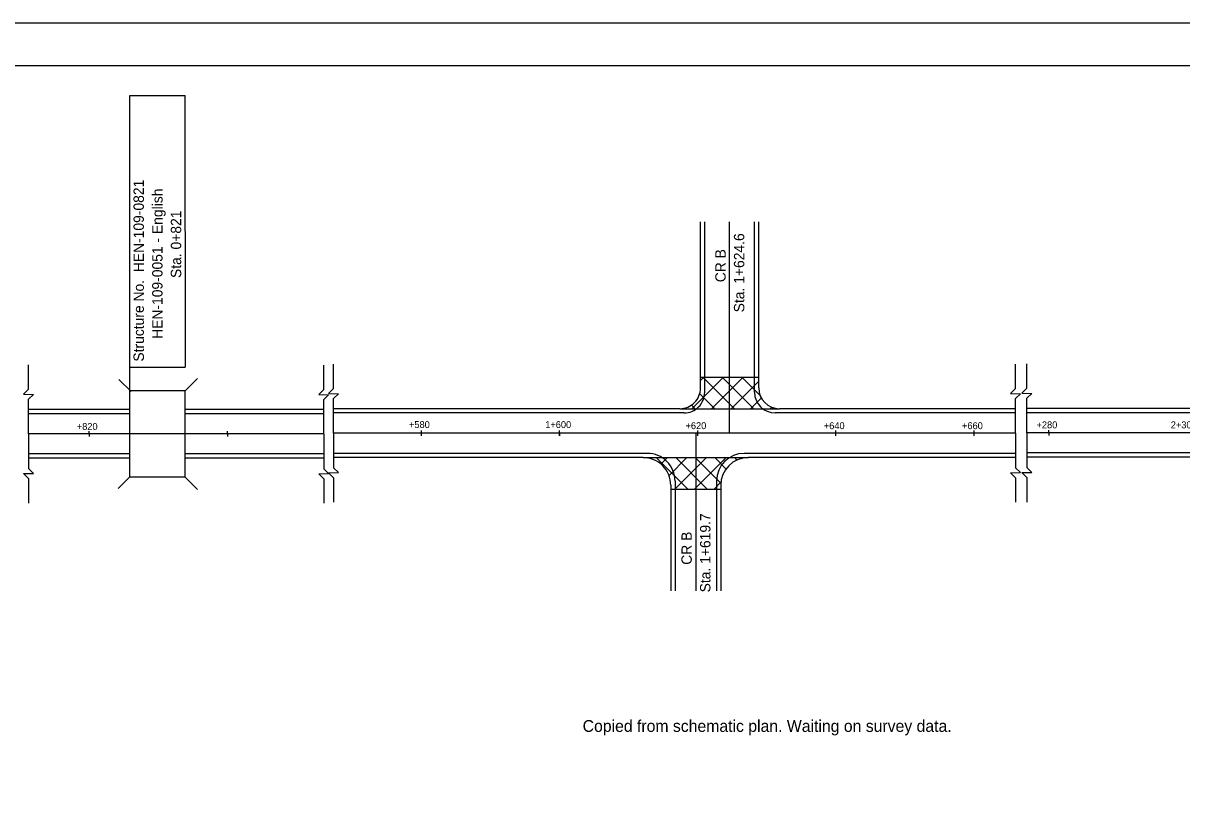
# Model space of a CAD drawing. Extents: x 3 to 683, y -6 to 434.
# Drawn here: x 176.6 to 451.7, y 251.3 to 433.7 of the extents above; entities that cross this region are included whole.
import ezdxf

# ---------------------------------------------------------------- set-up
doc = ezdxf.new("R2010")
doc.units = 0
for name, color, linetype in [('Default', 7, 'Continuous'), ('SH_Border', 7, 'Continuous'), ('SH_Cut_Line', 7, 'Continuous'), ('SH_Text', 7, 'Continuous')]:
    doc.layers.add(name, color=color, linetype=linetype)

msp = doc.modelspace()

# ---------------------------------------------------------------- linework, layer by layer
at = {"layer": 'Default'}
for p, q in [((201.91, 346.51), (201.91, 416.55)), ((201.91, 416.55), (215.04, 416.55)), ((215.06, 352.07), (215.02, 416.55)), ((337.38, 347.15), (337.38, 386.58)), ((338.38, 346.15), (338.38, 386.58)), ((344.28, 336.43), (344.28, 386.58)), ((350.19, 346.15), (350.19, 386.58)), ((351.19, 347.15), (351.19, 386.58)), ((177.82, 346.85), (177.82, 352.66)), ((247.9, 346.79), (247.9, 352.59)), ((250.25, 347.03), (250.25, 352.83)), ((412.16, 347.03), (412.16, 352.83)), ((414.87, 347.1), (414.87, 352.9)), ((201.93, 352.07), (215.05, 352.07)), ((215.04, 346.51), (217.94, 349.41)), ((335.35, 342.23), (342.84, 349.72)), ((337.38, 349.72), (351.19, 349.72)), ((337.38, 348.9), (338.2, 349.72)), ((337.91, 349.72), (345.41, 342.23)), ((339.98, 342.23), (347.48, 349.72)), ((342.55, 349.72), (350.05, 342.23)), ((347.19, 349.72), (351.69, 345.22)), ((176.64, 345.67), (177.82, 346.85)), ((199.26, 349.2), (202.16, 346.3)), ((246.72, 345.6), (247.9, 346.79)), ((249.06, 345.84), (250.25, 347.03)), ((344.62, 342.23), (351.19, 348.79)), ((410.98, 345.84), (412.16, 347.03)), ((413.68, 345.91), (414.87, 347.1)), ((176.64, 345.67), (178.98, 345.62)), ((177.82, 344.46), (178.98, 345.62)), ((177.82, 336.26), (177.82, 344.46)), ((201.91, 326), (201.91, 346.55)), ((215.04, 346.51), (201.91, 346.51)), ((215.04, 326), (215.04, 346.51)), ((246.72, 345.6), (249.06, 345.56)), ((247.9, 344.4), (249.06, 345.56)), ((247.9, 336.19), (247.9, 344.4)), ((249.06, 345.84), (251.41, 345.8)), ((250.25, 344.64), (251.41, 345.8)), ((250.25, 336.43), (250.25, 344.64)), ((337.22, 345.78), (340.77, 342.23)), ((349.26, 342.23), (351.85, 344.82)), ((410.98, 345.84), (413.32, 345.8)), ((412.16, 344.64), (413.32, 345.8)), ((412.16, 336.43), (412.16, 344.64)), ((413.68, 345.91), (416.03, 345.87)), ((414.87, 344.71), (416.03, 345.87)), ((414.87, 336.5), (414.87, 344.71)), ((201.91, 342.01), (177.82, 342.01)), ((247.9, 342.01), (215.04, 342.01)), ((332.45, 342.23), (250.25, 342.24)), ((333.45, 341.23), (250.25, 341.24)), ((332.45, 342.23), (356.11, 342.22)), ((335.25, 343.1), (336.13, 342.23)), ((353.9, 342.22), (354.23, 342.55)), ((354.39, 342.52), (354.69, 342.22)), ((372.33, 341.22), (355.11, 341.22)), ((372.33, 342.22), (356.11, 342.22)), ((412.16, 342.22), (372.33, 342.22)), ((412.16, 341.22), (372.33, 341.22)), ((468.32, 342.25), (414.87, 342.25)), ((468.32, 341.25), (414.87, 341.25)), ((201.91, 341.01), (177.82, 341.01)), ((247.9, 341.01), (215.04, 341.01)), ((177.82, 336.26), (177.82, 328.05)), ((247.9, 336.26), (177.82, 336.26)), ((192.24, 336.26), (192.24, 336.91)), ((192.24, 336.26), (192.24, 335.6)), ((225.05, 336.26), (225.05, 336.91)), ((225.05, 336.26), (225.05, 335.6)), ((247.9, 336.19), (247.9, 327.98)), ((412.16, 336.43), (250.25, 336.43)), ((250.25, 336.43), (250.25, 328.22)), ((271.12, 336.43), (271.12, 337.09)), ((271.12, 335.77), (271.12, 336.43)), ((303.93, 336.43), (303.93, 337.09)), ((303.93, 336.43), (303.93, 335.77)), ((303.93, 335.77), (303.93, 336.43)), ((336.24, 336.43), (336.24, 298.98)), ((336.74, 336.43), (336.74, 337.09)), ((336.74, 335.77), (336.74, 336.43)), ((369.54, 336.43), (369.54, 337.09)), ((369.54, 335.77), (369.54, 336.43)), ((402.35, 336.43), (402.35, 337.09)), ((402.35, 335.77), (402.35, 336.43)), ((412.16, 336.43), (412.16, 328.22)), ((532.92, 336.5), (414.87, 336.5)), ((414.87, 336.5), (414.87, 328.29)), ((420.09, 336.5), (420.09, 337.15)), ((420.09, 336.5), (420.09, 335.84)), ((201.91, 331.5), (177.82, 331.5)), ((201.91, 330.5), (177.82, 330.5)), ((247.9, 331.51), (215.04, 331.5)), ((247.9, 330.51), (215.04, 330.5)), ((324.76, 331.63), (250.25, 331.62)), ((323.76, 330.63), (250.25, 330.62)), ((323.76, 330.63), (348.73, 330.64)), ((324.76, 330.51), (324.88, 330.63)), ((326.86, 330.63), (334.35, 323.14)), ((327.96, 329.07), (329.52, 330.63)), ((329.9, 326.37), (334.16, 330.63)), ((331.3, 323.14), (338.8, 330.63)), ((331.5, 330.63), (338.99, 323.14)), ((335.94, 323.14), (343.44, 330.63)), ((336.13, 330.63), (342.19, 324.57)), ((340.77, 330.63), (343.49, 327.92)), ((345.41, 330.64), (346.02, 330.03)), ((372.33, 331.64), (347.72, 331.64)), ((347.99, 330.54), (348.08, 330.64)), ((372.33, 330.64), (348.73, 330.64)), ((412.16, 331.64), (372.33, 331.64)), ((412.16, 330.64), (372.33, 330.64)), ((468.32, 331.75), (414.87, 331.75)), ((468.32, 330.75), (414.87, 330.75)), ((177.82, 328.05), (178.98, 326.89)), ((247.9, 327.98), (249.06, 326.82)), ((250.25, 328.22), (251.41, 327.06)), ((412.16, 328.22), (413.32, 327.06)), ((414.87, 328.29), (416.03, 327.13)), ((176.64, 326.84), (178.98, 326.89)), ((176.64, 326.84), (177.82, 325.66)), ((177.82, 325.66), (177.82, 319.85)), ((199.08, 323.26), (201.83, 326)), ((215.04, 326), (201.91, 326)), ((215.04, 326), (217.94, 323.1)), ((246.72, 326.78), (249.06, 326.82)), ((246.72, 326.78), (247.9, 325.59)), ((247.9, 325.59), (247.9, 319.78)), ((249.06, 327.02), (251.41, 327.06)), ((249.06, 327.02), (250.25, 325.83)), ((250.25, 325.83), (250.25, 320.03)), ((331.32, 325.07), (331.32, 298.98)), ((340.58, 323.14), (342.22, 324.78)), ((341.16, 325.07), (341.16, 298.98)), ((410.98, 327.02), (413.32, 327.06)), ((410.98, 327.02), (412.16, 325.83)), ((412.16, 325.83), (412.16, 320.03)), ((413.68, 327.08), (416.03, 327.13)), ((413.68, 327.08), (414.87, 325.9)), ((414.87, 325.9), (414.87, 320.09)), ((330.32, 324.07), (330.32, 298.98)), ((330.32, 323.14), (342.17, 323.14)), ((342.17, 324.07), (342.17, 298.98))]:
    msp.add_line(p, q, dxfattribs=at)
for centre, radius, start, end in [((332.45, 347.15), 4.92, 269.9893, 0), ((356.11, 347.15), 4.92, 180, 269.9874), ((333.45, 346.15), 4.92, 269.9894, 0), ((355.11, 346.15), 4.92, 180, 269.9902), ((323.76, 324.07), 6.56, 0, 90.0091), ((324.76, 325.07), 6.56, 0, 90.0111), ((347.73, 325.07), 6.56, 90.0115, 180), ((348.73, 324.07), 6.56, 90.0119, 180)]:
    msp.add_arc(centre, radius, start, end, dxfattribs=at)
at = {"layer": 'SH_Border'}
msp.add_lwpolyline([(32.89, 423.72), (672.89, 423.72), (672.89, 3.72), (32.89, 3.72)], close=True, dxfattribs=at)
at = {"layer": 'SH_Cut_Line'}
msp.add_lwpolyline([(2.89, -6.28), (682.89, -6.28), (682.89, 433.72), (2.89, 433.72)], close=True, dxfattribs=at)

# ---------------------------------------------------------------- texts
at = {"layer": 'Default'}
for s, height, p in [('Structure No.  HEN-109-0821', 2.4606, (205.21, 353.41)), ('HEN-109-0051 - English', 2.4606, (209.64, 358.81)), ('Sta. 0+821', 2.461, (214.07, 373.25)), ('Sta. 1+624.6', 2.4606, (347.77, 365.11)), ('CR B', 2.461, (343.35, 372.25)), ('Sta. 1+619.7', 2.4606, (339.73, 298.65)), ('CR B', 2.461, (335.3, 305.19))]:
    msp.add_text(s, height=height, rotation=90, dxfattribs=at).set_placement(p)
for s, p in [('+820', (189.29, 337.2)), ('+580', (268.16, 337.64)), ('1+600', (300.51, 337.64)), ('+620', (333.81, 337.38)), ('+640', (366.65, 337.38)), ('+660', (399.46, 337.38)), ('+280', (417.15, 337.58)), ('2+300', (449.03, 337.58))]:
    msp.add_text(s, height=1.64, dxfattribs=at).set_placement(p)
at = {"layer": 'SH_Text'}
msp.add_text('Copied from schematic plan. Waiting on survey data.', height=2.8, dxfattribs=at).set_placement((309.39, 265.54))

doc.saveas('drawing.dxf')
